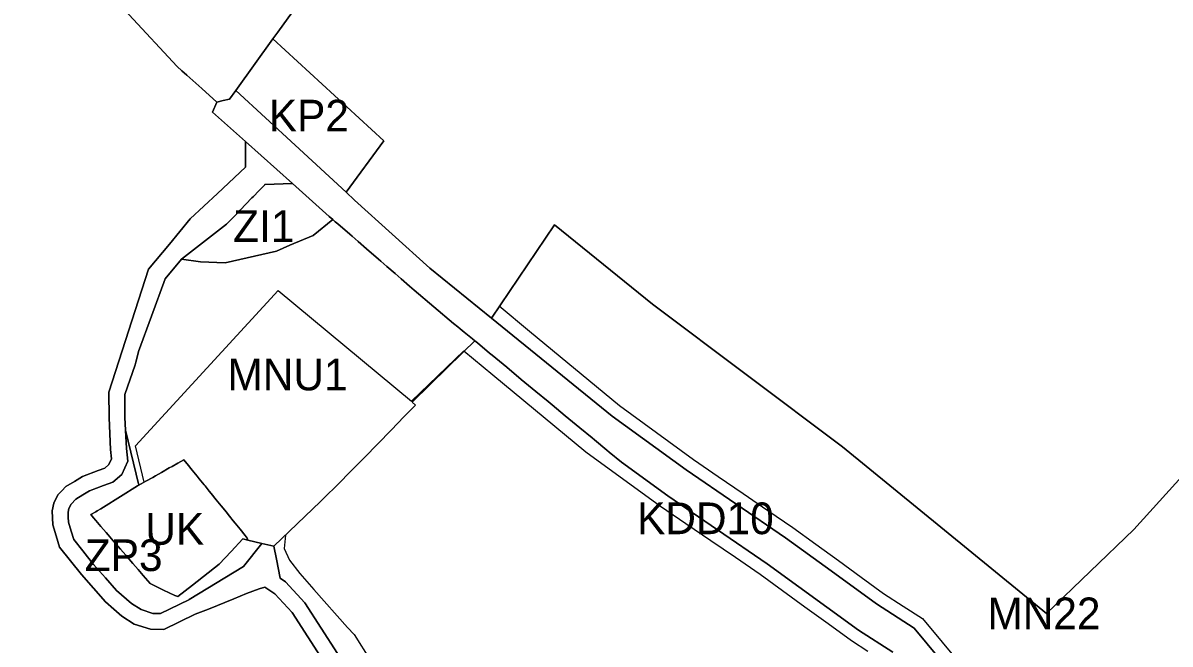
# Model space of a CAD drawing. Extents: x 7439486 to 7443435, y 5551288 to 5554556.
# Drawn here: x 7440456.7 to 7440818.3, y 5552708 to 5552903.8 of the extents above; entities that cross this region are included whole.
import ezdxf

# ---------------------------------------------------------------- set-up
doc = ezdxf.new("R2010")
doc.units = 0
for name, color, linetype in [('linie_rozgraniczajace', 7, 'Continuous'), ('linie_zabudowy_nieprzekraczalne', 7, 'Continuous'), ('oznaczenia_przeznaczen', 7, 'Continuous')]:
    doc.layers.add(name, color=color, linetype=linetype)

msp = doc.modelspace()

# ---------------------------------------------------------------- linework, layer by layer
at = {"layer": 'linie_rozgraniczajace'}
for points in [[(7440397.02, 5553005.21), (7440424.65, 5553013.44), (7440452.29, 5553021.67), (7440459.16, 5553014.57), (7440466.02, 5553007.47), (7440485.53, 5552988.06), (7440505.03, 5552968.66), (7440512.12, 5552961.61), (7440519.21, 5552954.56), (7440535.73, 5552938.31), (7440552.25, 5552922.07), (7440537.04, 5552900.92), (7440535.47, 5552898.74), (7440523.81, 5552882.54), (7440521.82, 5552879.78), (7440519.83, 5552879.3), (7440517.84, 5552878.81), (7440513.08, 5552883.09), (7440508.33, 5552887.36), (7440506.82, 5552888.72), (7440505.31, 5552890.07), (7440490.04, 5552906.49), (7440474.76, 5552922.91), (7440435.89, 5552964.06)], [(7440523.81, 5552882.54), (7440535.47, 5552898.74), (7440570.41, 5552866.67), (7440558.56, 5552850.4), (7440542.51, 5552865.24)], [(7440506.71, 5552829.35), (7440520.87, 5552840.33), (7440524.48, 5552844.07), (7440525.18, 5552844.79), (7440528.89, 5552848.62), (7440529.35, 5552849.1), (7440531.09, 5552850.9), (7440532.83, 5552852.69), (7440532.97, 5552852.84), (7440541.61, 5552853.16), (7440553.26, 5552842.76), (7440554.33, 5552841.83), (7440548.15, 5552836.81), (7440540.83, 5552833.72), (7440536.67, 5552831.87), (7440529.66, 5552830.29), (7440520.43, 5552828.2), (7440512.68, 5552828.51)], [(7440488.81, 5552779.42), (7440488.79, 5552786.66), (7440492.06, 5552796.03), (7440492.26, 5552796.85), (7440492.85, 5552799.27), (7440493.09, 5552800.25), (7440497.21, 5552811.34), (7440501.51, 5552823.1), (7440506.71, 5552829.35), (7440512.68, 5552828.51), (7440520.43, 5552828.2), (7440529.66, 5552830.29), (7440536.67, 5552831.87), (7440540.83, 5552833.72), (7440548.15, 5552836.81), (7440554.33, 5552841.83), (7440555.15, 5552841.12), (7440555.91, 5552840.47), (7440559.69, 5552837.19), (7440560.44, 5552836.54), (7440562.33, 5552834.9), (7440564.98, 5552832.61), (7440568.76, 5552829.34), (7440569.52, 5552828.69), (7440571.41, 5552827.05), (7440574.05, 5552824.76), (7440575.94, 5552823.12), (7440578.59, 5552820.83), (7440580.02, 5552819.59), (7440592.41, 5552809.08), (7440593.74, 5552808), (7440594.51, 5552807.36), (7440595.78, 5552806.32), (7440598.38, 5552804.25), (7440599.18, 5552803.57), (7440595.59, 5552800.09), (7440594.87, 5552799.39), (7440590.57, 5552795.21), (7440579.34, 5552784.29), (7440580.4, 5552783.34), (7440576.91, 5552779.76), (7440572.73, 5552775.46), (7440568.55, 5552771.16), (7440564.36, 5552766.86), (7440560.17, 5552762.56), (7440555.98, 5552758.27), (7440551.67, 5552754.1), (7440550.49, 5552752.95), (7440535.78, 5552738.83), (7440531.98, 5552739.73), (7440527.62, 5552740.75), (7440527.39, 5552741.41), (7440526.72, 5552742.23), (7440525.15, 5552744.18), (7440524.06, 5552745.53), (7440523.58, 5552746.12), (7440522.95, 5552746.9), (7440521.84, 5552748.27), (7440520.73, 5552749.65), (7440519.81, 5552750.79), (7440519.18, 5552751.57), (7440517.61, 5552753.51), (7440516.04, 5552755.45), (7440515.41, 5552756.23), (7440514.08, 5552757.88), (7440513.84, 5552758.18), (7440512.27, 5552760.12), (7440511.64, 5552760.9), (7440510.07, 5552762.84), (7440508.5, 5552764.79), (7440507.87, 5552765.56), (7440507.42, 5552766.12), (7440505.56, 5552765.06), (7440503.69, 5552764), (7440502.82, 5552763.51), (7440500.33, 5552762.1), (7440498.48, 5552761.04), (7440497.61, 5552760.55), (7440495.43, 5552759.31), (7440493.24, 5552758.07), (7440493.21, 5552758.06), (7440489, 5552775.46)], [(7440471.03, 5552746.46), (7440470.97, 5552748.01), (7440470.91, 5552749.57), (7440471.17, 5552750.78), (7440471.86, 5552752.13), (7440473.34, 5552753.71), (7440475.51, 5552755.03), (7440477.65, 5552756.33), (7440482.09, 5552757.98), (7440485.02, 5552759.07), (7440487.88, 5552761.47), (7440489.76, 5552765.66), (7440489.28, 5552769.7), (7440489, 5552775.46), (7440493.21, 5552758.06), (7440492.76, 5552757.93), (7440482.05, 5552751.18), (7440481.2, 5552750.66), (7440480.07, 5552749.99), (7440479.64, 5552749.73), (7440478.08, 5552748.8), (7440478.53, 5552748.28), (7440478.97, 5552747.76), (7440479.62, 5552747), (7440481.25, 5552745.11), (7440482.89, 5552743.21), (7440483.54, 5552742.46), (7440485.17, 5552740.56), (7440487.44, 5552737.93), (7440489.08, 5552736.02), (7440490.72, 5552734.12), (7440491.37, 5552733.36), (7440493, 5552731.47), (7440494.63, 5552729.58), (7440495.28, 5552728.82), (7440496.8, 5552727.06), (7440501.02, 5552725.01), (7440504.61, 5552723.28), (7440505.49, 5552722.96), (7440510.1, 5552726.58), (7440518.57, 5552733.24), (7440522.31, 5552737.18), (7440526.05, 5552741.13), (7440527.62, 5552740.75), (7440531.98, 5552739.73), (7440526.23, 5552732.48), (7440509.13, 5552722.01), (7440509.01, 5552721.96), (7440500, 5552717.64), (7440497.67, 5552717.65), (7440493.93, 5552718.86), (7440490.88, 5552720.81), (7440486.21, 5552724.86), (7440482.66, 5552728.9), (7440478.97, 5552733.1), (7440475.59, 5552737.36), (7440472.72, 5552740.97), (7440471.92, 5552743.57)], [(7440478.08, 5552748.8), (7440479.64, 5552749.73), (7440480.07, 5552749.99), (7440481.2, 5552750.66), (7440482.05, 5552751.18), (7440492.76, 5552757.93), (7440493.21, 5552758.06), (7440493.24, 5552758.07), (7440495.43, 5552759.31), (7440497.61, 5552760.55), (7440498.48, 5552761.04), (7440500.33, 5552762.1), (7440502.82, 5552763.51), (7440503.69, 5552764), (7440505.56, 5552765.06), (7440507.42, 5552766.12), (7440507.87, 5552765.56), (7440508.5, 5552764.79), (7440510.07, 5552762.84), (7440511.64, 5552760.9), (7440512.27, 5552760.12), (7440513.84, 5552758.18), (7440514.08, 5552757.88), (7440515.41, 5552756.23), (7440516.04, 5552755.45), (7440517.61, 5552753.51), (7440519.18, 5552751.57), (7440519.81, 5552750.79), (7440520.73, 5552749.65), (7440521.84, 5552748.27), (7440522.95, 5552746.9), (7440523.58, 5552746.12), (7440524.06, 5552745.53), (7440525.15, 5552744.18), (7440526.72, 5552742.23), (7440527.39, 5552741.41), (7440527.62, 5552740.75), (7440526.05, 5552741.13), (7440522.31, 5552737.18), (7440518.57, 5552733.24), (7440510.1, 5552726.58), (7440505.49, 5552722.96), (7440504.61, 5552723.28), (7440501.02, 5552725.01), (7440496.8, 5552727.06), (7440495.28, 5552728.82), (7440494.63, 5552729.58), (7440493, 5552731.47), (7440491.37, 5552733.36), (7440490.72, 5552734.12), (7440489.08, 5552736.02), (7440487.44, 5552737.93), (7440485.17, 5552740.56), (7440483.54, 5552742.46), (7440482.89, 5552743.21), (7440481.25, 5552745.11), (7440479.62, 5552747), (7440478.97, 5552747.76), (7440478.53, 5552748.28)]]:
    msp.add_lwpolyline(points, close=True, dxfattribs=at)
for points in [[(7440584.98, 5552826.49), (7440561.22, 5552847.94), (7440558.56, 5552850.4), (7440570.41, 5552866.67), (7440535.47, 5552898.74), (7440537.04, 5552900.92), (7440552.25, 5552922.07)], [(7440490.04, 5552906.49), (7440505.31, 5552890.07), (7440506.82, 5552888.72), (7440508.33, 5552887.36), (7440513.08, 5552883.09), (7440517.84, 5552878.81), (7440516.44, 5552875.62), (7440526.8, 5552866.38), (7440526.88, 5552858.28), (7440517.99, 5552849.99), (7440509.43, 5552842.01), (7440502.83, 5552834.07), (7440496.23, 5552826.14), (7440483.79, 5552787.44), (7440483.81, 5552779.29), (7440484.3, 5552769.29), (7440484.63, 5552766.44), (7440483.79, 5552764.56), (7440482.47, 5552763.45), (7440480.36, 5552762.67), (7440475.46, 5552760.86), (7440472.91, 5552759.3), (7440470.16, 5552757.63), (7440468.94, 5552756.33), (7440467.72, 5552755.03), (7440466.42, 5552752.47), (7440465.89, 5552750), (7440465.97, 5552747.81), (7440466.06, 5552745.61), (7440467.14, 5552742.1), (7440468.22, 5552738.59), (7440471.68, 5552734.24), (7440475.14, 5552729.89), (7440478.91, 5552725.6), (7440482.68, 5552721.31), (7440485.28, 5552719.05), (7440487.88, 5552716.8), (7440491.78, 5552714.3), (7440496.87, 5552712.66), (7440501.12, 5552712.64), (7440511.02, 5552717.38), (7440515.15, 5552719.04), (7440523.17, 5552722.25), (7440527.19, 5552723.92), (7440531.19, 5552725.46), (7440532.9, 5552725.99), (7440536.13, 5552723.82), (7440541.58, 5552717.93), (7440551.41, 5552702.61)], [(7440989.22, 5552908.83), (7440965.44, 5552870.5), (7440926.32, 5552811.77), (7440905.79, 5552780.95), (7440904.96, 5552781.81), (7440896.16, 5552791.04), (7440869.94, 5552813.34), (7440868.45, 5552811.74), (7440866.41, 5552809.54), (7440856.33, 5552798.67), (7440854.44, 5552796.59), (7440806.91, 5552744.07), (7440779.37, 5552717.67), (7440747.23, 5552743.93), (7440715.09, 5552770.19), (7440685.13, 5552792.67), (7440655.16, 5552815.15), (7440624.24, 5552840.11), (7440604.41, 5552810.75), (7440584.98, 5552826.49)], [(7440730.92, 5552705.44), (7440720.13, 5552712.42), (7440691.36, 5552733.33), (7440660.03, 5552754.74), (7440645.4, 5552765.35), (7440641.55, 5552768.5), (7440640.78, 5552769.14), (7440636.93, 5552772.33), (7440636.15, 5552772.97), (7440632.3, 5552776.15), (7440627.68, 5552779.98), (7440623.54, 5552783.4), (7440622.29, 5552784.44), (7440618.43, 5552787.62), (7440613.81, 5552791.45), (7440609.19, 5552795.27), (7440604.57, 5552799.1), (7440603.79, 5552799.73), (7440599.94, 5552802.92), (7440599.18, 5552803.57), (7440598.38, 5552804.25), (7440595.78, 5552806.32), (7440594.51, 5552807.36), (7440593.74, 5552808), (7440592.41, 5552809.08), (7440580.02, 5552819.59), (7440578.59, 5552820.83), (7440575.94, 5552823.12), (7440574.05, 5552824.76), (7440571.41, 5552827.05), (7440569.52, 5552828.69), (7440568.76, 5552829.34), (7440564.98, 5552832.61), (7440562.33, 5552834.9), (7440560.44, 5552836.54), (7440559.69, 5552837.19), (7440555.91, 5552840.47), (7440555.15, 5552841.12), (7440554.33, 5552841.83), (7440553.26, 5552842.76), (7440541.61, 5552853.16), (7440526.8, 5552866.38), (7440516.44, 5552875.62), (7440517.84, 5552878.81), (7440519.83, 5552879.3), (7440521.82, 5552879.78), (7440523.81, 5552882.54), (7440542.51, 5552865.24), (7440558.56, 5552850.4), (7440561.22, 5552847.94), (7440584.98, 5552826.49), (7440604.41, 5552810.75), (7440642.48, 5552779.89), (7440665.79, 5552762.91), (7440681.46, 5552752.21), (7440697.12, 5552741.5), (7440711.46, 5552731.08), (7440725.79, 5552720.67), (7440737.63, 5552713.01), (7440749.48, 5552698.79)], [(7440466.06, 5552745.61), (7440465.97, 5552747.81), (7440465.89, 5552750), (7440466.42, 5552752.47), (7440467.72, 5552755.03), (7440468.94, 5552756.33), (7440470.16, 5552757.63), (7440472.91, 5552759.3), (7440475.46, 5552760.86), (7440480.36, 5552762.67), (7440482.47, 5552763.45), (7440483.79, 5552764.56), (7440484.63, 5552766.44), (7440484.3, 5552769.29), (7440483.81, 5552779.29), (7440483.79, 5552787.44), (7440496.23, 5552826.14), (7440502.83, 5552834.07), (7440509.43, 5552842.01), (7440517.99, 5552849.99), (7440526.88, 5552858.28), (7440526.8, 5552866.38), (7440541.61, 5552853.16), (7440532.97, 5552852.84), (7440532.83, 5552852.69), (7440531.09, 5552850.9), (7440529.35, 5552849.1), (7440528.89, 5552848.62), (7440525.18, 5552844.79), (7440524.48, 5552844.07), (7440520.87, 5552840.33), (7440506.71, 5552829.35), (7440501.51, 5552823.1), (7440497.21, 5552811.34), (7440493.09, 5552800.25), (7440492.85, 5552799.27), (7440492.26, 5552796.85), (7440492.06, 5552796.03), (7440488.79, 5552786.66), (7440488.81, 5552779.42), (7440489, 5552775.46), (7440489.28, 5552769.7), (7440489.76, 5552765.66), (7440487.88, 5552761.47), (7440485.02, 5552759.07), (7440482.09, 5552757.98), (7440477.65, 5552756.33), (7440475.51, 5552755.03), (7440473.34, 5552753.71), (7440471.86, 5552752.13), (7440471.17, 5552750.78), (7440470.91, 5552749.57), (7440470.97, 5552748.01), (7440471.03, 5552746.46), (7440471.92, 5552743.57), (7440472.72, 5552740.97), (7440475.59, 5552737.36), (7440478.97, 5552733.1), (7440482.66, 5552728.9), (7440486.21, 5552724.86), (7440490.88, 5552720.81), (7440493.93, 5552718.86), (7440497.67, 5552717.65), (7440500, 5552717.64), (7440509.01, 5552721.96), (7440509.13, 5552722.01), (7440526.23, 5552732.48), (7440531.98, 5552739.73), (7440535.78, 5552738.83), (7440536.58, 5552734.75), (7440537.77, 5552728.74), (7440539.41, 5552727.65), (7440545.55, 5552721), (7440555.8, 5552705.02)], [(7440749.48, 5552698.79), (7440737.63, 5552713.01), (7440725.79, 5552720.67), (7440711.46, 5552731.08), (7440697.12, 5552741.5), (7440681.46, 5552752.21), (7440665.79, 5552762.91), (7440642.48, 5552779.89), (7440604.41, 5552810.75), (7440624.24, 5552840.11), (7440655.16, 5552815.15), (7440685.13, 5552792.67), (7440715.09, 5552770.19), (7440747.23, 5552743.93), (7440779.37, 5552717.67), (7440806.91, 5552744.07), (7440854.44, 5552796.59)], [(7440555.8, 5552705.02), (7440545.55, 5552721), (7440539.41, 5552727.65), (7440537.77, 5552728.74), (7440536.58, 5552734.75), (7440535.78, 5552738.83), (7440550.49, 5552752.95), (7440551.67, 5552754.1), (7440555.98, 5552758.27), (7440560.17, 5552762.56), (7440564.36, 5552766.86), (7440568.55, 5552771.16), (7440572.73, 5552775.46), (7440576.91, 5552779.76), (7440580.4, 5552783.34), (7440579.34, 5552784.29), (7440590.57, 5552795.21), (7440594.87, 5552799.39), (7440595.59, 5552800.09), (7440599.18, 5552803.57), (7440599.94, 5552802.92), (7440603.79, 5552799.73), (7440604.57, 5552799.1), (7440609.19, 5552795.27), (7440613.81, 5552791.45), (7440618.43, 5552787.62), (7440622.29, 5552784.44), (7440623.54, 5552783.4), (7440627.68, 5552779.98), (7440632.3, 5552776.15), (7440636.15, 5552772.97), (7440636.93, 5552772.33), (7440640.78, 5552769.14), (7440641.55, 5552768.5), (7440645.4, 5552765.35), (7440660.03, 5552754.74), (7440691.36, 5552733.33), (7440720.13, 5552712.42), (7440730.92, 5552705.44)], [(7440551.41, 5552702.61), (7440541.58, 5552717.93), (7440536.13, 5552723.82), (7440532.9, 5552725.99), (7440531.19, 5552725.46), (7440527.19, 5552723.92), (7440523.17, 5552722.25), (7440515.15, 5552719.04), (7440511.02, 5552717.38), (7440501.12, 5552712.64), (7440496.87, 5552712.66), (7440491.78, 5552714.3), (7440487.88, 5552716.8), (7440485.28, 5552719.05), (7440482.68, 5552721.31), (7440478.91, 5552725.6), (7440475.14, 5552729.89), (7440471.68, 5552734.24), (7440468.22, 5552738.59), (7440467.14, 5552742.1), (7440466.06, 5552745.61)]]:
    msp.add_lwpolyline(points, dxfattribs=at)
at = {"layer": 'linie_zabudowy_nieprzekraczalne'}
for points in [[(7440494.92, 5552759.02), (7440492.19, 5552770.49), (7440537.18, 5552819.42), (7440579.16, 5552784.55), (7440595.69, 5552800.47), (7440604.82, 5552792.91), (7440634.14, 5552768.65), (7440657.72, 5552751.48), (7440665.64, 5552746.06), (7440673.56, 5552740.65), (7440681.31, 5552735.35), (7440689.06, 5552730.06), (7440696.14, 5552724.91), (7440703.23, 5552719.76), (7440710.55, 5552714.44), (7440717.87, 5552709.12), (7440723.05, 5552705.76)], [(7440606.84, 5552814.6), (7440616.41, 5552806.68), (7440644.74, 5552783.2), (7440656.42, 5552774.69), (7440668.1, 5552766.18), (7440675.9, 5552760.85), (7440683.71, 5552755.51), (7440691.57, 5552750.14), (7440699.43, 5552744.77), (7440706.62, 5552739.54), (7440713.81, 5552734.32), (7440720.93, 5552729.14), (7440728.05, 5552723.96), (7440734.18, 5552720), (7440740.31, 5552716.04), (7440746.47, 5552708.65), (7440752.63, 5552701.26)], [(7440539.41, 5552742.31), (7440539.01, 5552738.12), (7440540.7, 5552734.4), (7440543.93, 5552730.28), (7440548.44, 5552725.16), (7440559.05, 5552713.19), (7440561.07, 5552711), (7440566.29, 5552702.8), (7440572.6, 5552671.99), (7440572.58, 5552673.36), (7440596.55, 5552661.58), (7440601.67, 5552655.98), (7440611.96, 5552647.95), (7440623.63, 5552640.2), (7440635.29, 5552627.69), (7440648.86, 5552614.97), (7440664.34, 5552599.09), (7440679.83, 5552583.2), (7440689.79, 5552571.77), (7440694.38, 5552565.16), (7440698.84, 5552554.21), (7440703.98, 5552536.83), (7440704.57, 5552535.21), (7440707.81, 5552530.22)]]:
    msp.add_lwpolyline(points, dxfattribs=at)

# ---------------------------------------------------------------- texts
at = {"layer": 'oznaczenia_przeznaczen'}
for s, p in [('KP2', (7440534.18, 5552869.57)), ('ZI1', (7440522.95, 5552834.74)), ('MNU1', (7440521.15, 5552787.98)), ('KDD10', (7440650.29, 5552742.64)), ('UK', (7440495.24, 5552739.31)), ('ZP3', (7440476.17, 5552731.02)), ('MN22', (7440760.75, 5552712.67))]:
    msp.add_text(s, height=10, dxfattribs=at).set_placement(p)

doc.saveas('drawing.dxf')
